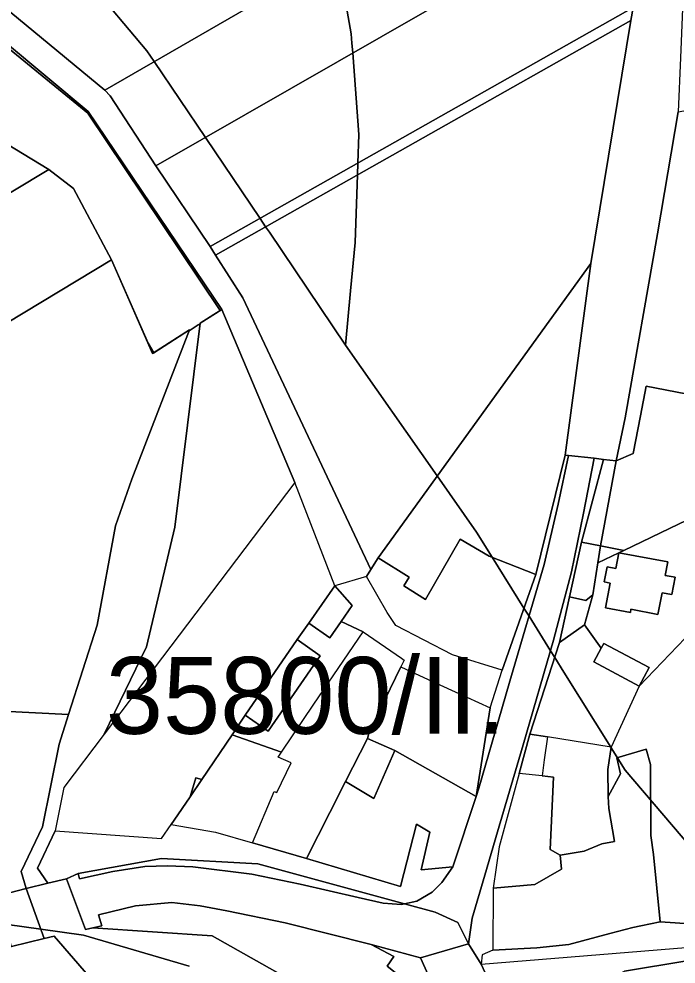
# Model space of a CAD drawing. Extents: x -522079 to -518792, y -1142400 to -1139961.
# Drawn here: x -520476.1 to -520347.8, y -1140798.1 to -1140613.6 of the extents above; entities that cross this region are included whole.
import ezdxf

# ---------------------------------------------------------------- set-up
doc = ezdxf.new("R2010")
doc.units = 0
for name, color, linetype in [('Bonity', 7, 'Continuous'), ('Hranice parcel', 7, 'Continuous'), ('Parcelní čísla', 7, 'Continuous'), ('Poz předměty', 7, 'Continuous'), ('Vnitřní kresba', 7, 'Continuous'), ('Značky bodu BP', 7, 'Continuous'), ('Značky kultur', 7, 'Continuous')]:
    doc.layers.add(name, color=color, linetype=linetype)

msp = doc.modelspace()

# ---------------------------------------------------------------- linework, layer by layer
at = {"layer": 'Bonity'}
msp.add_lwpolyline([(-520482.03, -1140698.6), (-520492.24, -1140681.28), (-520457.96, -1140660.67), (-520449.96, -1140678.96), (-520442.74, -1140674.34), (-520454.03, -1140703.46), (-520457.2, -1140712.56), (-520460.77, -1140732), (-520466.36, -1140749.44), (-520479.24, -1140748.79), (-520495.27, -1140747.98), (-520489.4, -1140725.83), (-520488.36, -1140721.89)], close=True, dxfattribs=at)
at = {"layer": 'Hranice parcel'}
for points in [[(-520307.77, -1140486.46), (-520327.66, -1140534.75), (-520331.42, -1140543.88), (-520333.94, -1140551.84), (-520337.95, -1140565.45), (-520342.68, -1140587.14), (-520346.39, -1140608.35), (-520346.89, -1140621.24), (-520347.36, -1140631.75), (-520351.39, -1140655.57), (-520357.72, -1140691.49), (-520359.48, -1140699.91), (-520361.97, -1140699.61), (-520363.79, -1140699.4), (-520368.79, -1140698.83), (-520369.41, -1140698.76), (-520364.42, -1140661.36), (-520356.59, -1140613.91), (-520356.14, -1140611.39), (-520352.4, -1140586.73), (-520348.21, -1140563.43), (-520342.62, -1140543.01), (-520328.73, -1140508.82)], [(-520587.65, -1140510.13), (-520562.49, -1140540.48), (-520557.7, -1140546.26), (-520503.8, -1140590.78), (-520490.09, -1140602.11), (-520459.31, -1140627.54), (-520458.26, -1140628.64), (-520449.35, -1140642.33), (-520438.76, -1140658.07), (-520437.69, -1140659.73), (-520432.32, -1140668.06), (-520407.37, -1140721.08), (-520408.23, -1140722.45), (-520414.39, -1140724.32), (-520422.23, -1140704.1), (-520436.48, -1140670.33), (-520462.54, -1140631.68), (-520560.63, -1140549.81), (-520611.7, -1140490.5)], [(-520408.23, -1140722.45), (-520414.39, -1140724.32)], [(-520381.74, -1140740.77), (-520391.43, -1140737.8), (-520402.49, -1140732.06), (-520404.15, -1140729.51), (-520408.23, -1140722.45)], [(-520414.39, -1140724.32), (-520419.44, -1140731.56)], [(-520413.15, -1140731.24), (-520410.99, -1140728.16), (-520414.39, -1140724.32)], [(-520414.39, -1140724.32), (-520410.99, -1140728.16), (-520413.15, -1140731.24)], [(-520419.44, -1140731.56), (-520421.72, -1140734.81)], [(-520419.44, -1140731.56), (-520415.38, -1140734.43)], [(-520415.38, -1140734.43), (-520419.44, -1140731.56)], [(-520415.38, -1140734.43), (-520413.15, -1140731.24)], [(-520413.15, -1140731.24), (-520415.38, -1140734.43)], [(-520413.15, -1140731.24), (-520408.83, -1140733.26)], [(-520408.83, -1140733.26), (-520413.15, -1140731.24)], [(-520424.83, -1140756.78), (-520418.47, -1140747.39), (-520408.83, -1140733.26)], [(-520408.83, -1140733.26), (-520401.38, -1140738.43), (-520400.87, -1140738.78), (-520401.52, -1140740.13)], [(-520421.72, -1140734.81), (-520431.9, -1140749.57)], [(-520417.23, -1140737.96), (-520421.72, -1140734.81)], [(-520421.72, -1140734.81), (-520417.23, -1140737.96)], [(-520427.38, -1140752.69), (-520417.23, -1140737.96)], [(-520417.23, -1140737.96), (-520427.38, -1140752.69)], [(-520401.52, -1140740.13), (-520396.18, -1140742.58), (-520390.88, -1140745.01), (-520384.05, -1140748.14)], [(-520384.05, -1140748.14), (-520381.74, -1140740.77)], [(-520431.9, -1140749.57), (-520434.44, -1140753.41)], [(-520431.9, -1140749.57), (-520427.38, -1140752.69)], [(-520427.38, -1140752.69), (-520431.9, -1140749.57)], [(-520434.44, -1140753.41), (-520440.36, -1140762.11)], [(-520434.44, -1140753.41), (-520424.83, -1140756.78)], [(-520424.83, -1140756.78), (-520434.44, -1140753.41)], [(-520372.89, -1140753.81), (-520373.51, -1140758.29), (-520373.94, -1140761.39)], [(-520360.42, -1140755.8), (-520372.89, -1140753.81)], [(-520361.04, -1140765.41), (-520361.11, -1140760.14), (-520360.42, -1140755.8)], [(-520350.89, -1140789.92), (-520352.17, -1140776.77), (-520352.71, -1140773.02), (-520352.78, -1140759.2), (-520353.64, -1140756.21), (-520359.31, -1140757.88), (-520358.59, -1140760.98), (-520361.04, -1140765.41)], [(-520430.49, -1140774.45), (-520426.25, -1140764.44), (-520425.69, -1140764.63), (-520422.94, -1140758.87), (-520425.43, -1140757.74), (-520424.83, -1140756.78)], [(-520440.36, -1140762.11), (-520441.56, -1140761.77), (-520442.66, -1140765.49)], [(-520373.94, -1140761.39), (-520371.72, -1140761.64), (-520372.32, -1140775.75), (-520370.42, -1140776.86)], [(-520442.66, -1140765.49), (-520440.36, -1140762.11)], [(-520440.36, -1140762.11), (-520442.66, -1140765.49)], [(-520442.66, -1140765.49), (-520445.76, -1140770.03), (-520446.34, -1140770.88)], [(-520370.42, -1140776.86), (-520365.71, -1140776.1), (-520362.27, -1140774.68), (-520359.77, -1140774.23), (-520360.88, -1140767.78), (-520361.04, -1140765.41)], [(-520361.04, -1140765.41), (-520360.88, -1140767.78), (-520359.77, -1140774.23)], [(-520626.37, -1140766.52), (-520614.11, -1140775.58), (-520593.15, -1140785.04), (-520568.68, -1140791.66), (-520556.98, -1140793.85), (-520544.08, -1140795.45), (-520533.1, -1140795.95), (-520521.89, -1140795.42), (-520508.09, -1140793.94), (-520497.35, -1140791.93), (-520485.15, -1140788.87), (-520482.88, -1140787.7), (-520480.98, -1140785.01), (-520474.64, -1140783.36), (-520471.14, -1140793.15), (-520477.5, -1140794.69), (-520477.93, -1140793.38), (-520487.57, -1140796.09), (-520495.6, -1140797.79), (-520508.3, -1140799.99)], [(-520446.34, -1140770.88), (-520437.68, -1140772.4), (-520430.49, -1140774.45)], [(-520362.27, -1140774.68), (-520365.71, -1140776.1)], [(-520359.77, -1140774.23), (-520362.27, -1140774.68)], [(-520365.71, -1140776.1), (-520370.42, -1140776.86)], [(-520370.42, -1140776.86), (-520370.11, -1140779.64), (-520375.33, -1140782.59)], [(-520383.46, -1140783.32), (-520383.53, -1140795.4)], [(-520375.33, -1140782.59), (-520383.46, -1140783.32)], [(-520368.73, -1140794.29), (-520360.72, -1140792.17), (-520356.2, -1140791.03), (-520354.62, -1140790.65), (-520350.89, -1140789.92)], [(-520350.89, -1140789.92), (-520354.62, -1140790.65), (-520356.2, -1140791.03), (-520360.72, -1140792.17), (-520368.73, -1140794.29)], [(-520332.51, -1140791.1), (-520350.89, -1140789.92)], [(-520385.85, -1140798.14), (-520333.88, -1140793.93), (-520323.97, -1140803.87)], [(-520383.53, -1140795.4), (-520374.96, -1140794.94), (-520368.73, -1140794.29)], [(-520368.73, -1140794.29), (-520374.96, -1140794.94), (-520383.53, -1140795.4)], [(-520383.53, -1140795.4), (-520385.62, -1140796.31), (-520385.85, -1140798.14)]]:
    msp.add_lwpolyline(points, dxfattribs=at)
for points in [[(-520343.7, -1140699.72), (-520340.94, -1140698.56), (-520339.07, -1140702.89), (-520335.84, -1140701.48), (-520334.3, -1140706.02), (-520336.43, -1140707.04), (-520344.29, -1140710.82), (-520347.29, -1140712.26), (-520357.97, -1140717.4), (-520362.54, -1140716.5), (-520359.48, -1140699.91), (-520356.12, -1140698.44), (-520354.71, -1140691.1), (-520353.6, -1140685.32), (-520345.87, -1140686.81), (-520341.7, -1140687.61), (-520339.66, -1140692.44), (-520345.67, -1140694.97)], [(-520394.79, -1140788), (-520400.82, -1140786.35), (-520398.38, -1140785.83), (-520395.36, -1140784.1), (-520393.48, -1140782.23), (-520391.38, -1140779.15), (-520386.83, -1140765.41), (-520386.29, -1140763.79), (-520381.78, -1140748.3), (-520380.21, -1140742.93), (-520373.52, -1140720.12), (-520370.77, -1140708.37), (-520368.79, -1140698.83), (-520363.79, -1140699.4), (-520365.84, -1140710.09), (-520368.19, -1140721.56), (-520371.69, -1140734.94), (-520377.6, -1140755.34), (-520382.64, -1140772.35), (-520385.08, -1140780.78), (-520387.56, -1140789.2), (-520388.29, -1140794.2), (-520390.4, -1140790.05)], [(-520386.83, -1140765.41), (-520384.05, -1140748.14), (-520381.74, -1140740.77), (-520375.15, -1140722.06), (-520369.41, -1140698.76), (-520368.79, -1140698.83), (-520370.77, -1140708.37), (-520373.52, -1140720.12), (-520380.21, -1140742.93), (-520381.78, -1140748.3), (-520386.29, -1140763.79)], [(-520383.46, -1140783.32), (-520383.53, -1140795.4), (-520385.62, -1140796.31), (-520385.85, -1140798.14), (-520388.29, -1140794.2), (-520387.56, -1140789.2), (-520385.08, -1140780.78), (-520382.64, -1140772.35), (-520377.6, -1140755.34), (-520371.69, -1140734.94), (-520368.19, -1140721.56), (-520365.84, -1140710.09), (-520363.79, -1140699.4), (-520361.97, -1140699.61), (-520366.26, -1140715.78), (-520368.57, -1140726.47), (-520370.5, -1140735.37), (-520376.29, -1140753.27), (-520378.38, -1140760.91), (-520382.29, -1140775.26)], [(-520366.26, -1140715.78), (-520361.97, -1140699.61), (-520359.48, -1140699.91), (-520362.54, -1140716.5)], [(-520381.74, -1140740.77), (-520391.43, -1140737.8), (-520402.49, -1140732.06), (-520404.15, -1140729.51), (-520408.23, -1140722.45), (-520407.37, -1140721.08), (-520405.96, -1140718.81), (-520399.85, -1140722.62), (-520400.9, -1140724.3), (-520396.68, -1140726.94), (-520389.9, -1140715.22), (-520384.29, -1140718.48), (-520375.15, -1140722.06)], [(-520368.57, -1140726.47), (-520366.26, -1140715.78), (-520362.54, -1140716.5), (-520363.02, -1140719.82), (-520364.02, -1140726.04), (-520365.37, -1140727.18)], [(-520357.97, -1140717.4), (-520358.95, -1140717.87), (-520363.02, -1140719.82), (-520362.54, -1140716.5)], [(-520358.95, -1140717.87), (-520349.37, -1140719.63), (-520349.88, -1140722.27), (-520347.97, -1140722.63), (-520348.59, -1140726.01), (-520350.51, -1140725.65), (-520351.32, -1140729.89), (-520356.58, -1140728.88), (-520356.67, -1140729.48), (-520361.57, -1140728.6), (-520360.67, -1140723.75), (-520361.8, -1140723.5), (-520361.21, -1140720.62), (-520359.53, -1140720.91)], [(-520365.37, -1140727.18), (-520364.02, -1140726.04), (-520365.68, -1140731.9), (-520370.5, -1140735.37), (-520368.57, -1140726.47)], [(-520365.68, -1140731.9), (-520362.41, -1140736.49), (-520363.84, -1140739.14), (-520354.98, -1140743.86), (-520360.42, -1140755.8), (-520372.89, -1140753.81), (-520376.29, -1140753.27), (-520370.5, -1140735.37)], [(-520407.68, -1140752.84), (-520408.04, -1140754.09), (-520412.32, -1140762.52), (-520415.37, -1140768.55), (-520419.92, -1140777.53), (-520430.49, -1140774.45), (-520426.25, -1140764.44), (-520425.69, -1140764.63), (-520422.94, -1140758.87), (-520425.43, -1140757.74), (-520424.83, -1140756.78), (-520418.47, -1140747.39), (-520408.83, -1140733.26), (-520401.38, -1140738.43), (-520400.87, -1140738.78), (-520401.52, -1140740.13)], [(-520361.88, -1140735.57), (-520353.05, -1140740.25), (-520354.98, -1140743.86), (-520363.84, -1140739.14), (-520362.41, -1140736.49)], [(-520386.83, -1140765.41), (-520402.66, -1140756.46), (-520408.04, -1140754.09), (-520407.68, -1140752.84), (-520401.52, -1140740.13), (-520396.18, -1140742.58), (-520390.88, -1140745.01), (-520384.05, -1140748.14)], [(-520480.98, -1140785.01), (-520484.92, -1140786.1), (-520485.38, -1140782.23), (-520498.09, -1140783.57), (-520499.08, -1140774.22), (-520498.32, -1140766.26), (-520497.66, -1140759.42), (-520497.51, -1140757.87), (-520496.94, -1140755.37), (-520495.27, -1140747.98), (-520479.24, -1140748.79), (-520466.36, -1140749.44), (-520468.2, -1140755.18), (-520471.47, -1140771.35), (-520475.64, -1140780.08), (-520474.64, -1140783.36)], [(-520412.32, -1140762.52), (-520408.04, -1140754.09), (-520402.66, -1140756.46), (-520406.78, -1140765.84)], [(-520372.89, -1140753.81), (-520373.51, -1140758.29), (-520373.94, -1140761.39), (-520378.38, -1140760.91), (-520376.29, -1140753.27)], [(-520419.92, -1140777.53), (-520415.37, -1140768.55), (-520412.32, -1140762.52), (-520406.78, -1140765.84), (-520402.66, -1140756.46), (-520386.83, -1140765.41), (-520391.38, -1140779.15), (-520397.56, -1140779.72), (-520395.82, -1140772.4), (-520398.45, -1140770.83), (-520401.54, -1140783.02)], [(-520470.41, -1140782.37), (-520472.47, -1140779.4), (-520468.98, -1140772.14), (-520448.2, -1140773.61), (-520446.34, -1140770.88), (-520437.68, -1140772.4), (-520430.49, -1140774.45), (-520419.92, -1140777.53), (-520401.54, -1140783.02), (-520398.45, -1140770.83), (-520395.82, -1140772.4), (-520397.56, -1140779.72), (-520391.38, -1140779.15), (-520393.48, -1140782.23), (-520395.36, -1140784.1), (-520398.38, -1140785.83), (-520400.82, -1140786.35), (-520429.44, -1140778.54), (-520448.23, -1140777.51), (-520464.48, -1140780.47), (-520466.78, -1140781.53)], [(-520400.82, -1140786.35), (-520401.42, -1140786.48), (-520404.95, -1140786.22), (-520409.82, -1140785.14), (-520421.16, -1140782.56), (-520430.59, -1140780.58), (-520442.14, -1140779.17), (-520447.03, -1140778.94), (-520451.46, -1140779.1), (-520457.74, -1140780.06), (-520464.21, -1140781.48), (-520464.48, -1140780.47), (-520448.23, -1140777.51), (-520429.44, -1140778.54)], [(-520407.29, -1140794.34), (-520424.08, -1140790.09), (-520435.45, -1140787.73), (-520440.68, -1140786.74), (-520446.22, -1140786.13), (-520453.31, -1140786.74), (-520460.51, -1140788.53), (-520459.9, -1140790.65), (-520461.64, -1140791.05), (-520463.08, -1140791.37), (-520466.78, -1140781.53), (-520464.48, -1140780.47), (-520464.21, -1140781.48), (-520457.74, -1140780.06), (-520451.46, -1140779.1), (-520447.03, -1140778.94), (-520442.14, -1140779.17), (-520430.59, -1140780.58), (-520421.16, -1140782.56), (-520409.82, -1140785.14), (-520404.95, -1140786.22), (-520401.42, -1140786.48), (-520400.82, -1140786.35), (-520394.79, -1140788), (-520390.4, -1140790.05), (-520388.29, -1140794.2), (-520397.69, -1140796.9)], [(-520461.64, -1140791.05), (-520459.9, -1140790.65), (-520460.51, -1140788.53), (-520453.31, -1140786.74), (-520446.22, -1140786.13), (-520440.68, -1140786.74), (-520435.45, -1140787.73), (-520424.08, -1140790.09), (-520407.29, -1140794.34), (-520402.86, -1140796.64), (-520404.19, -1140798.55), (-520401.05, -1140800.99), (-520400.31, -1140802.09), (-520404.93, -1140803.86), (-520413.92, -1140809.23), (-520421.04, -1140802.37), (-520438.34, -1140792.64)], [(-520479.52, -1140802.35), (-520481.31, -1140802.54), (-520492.42, -1140803.71), (-520483.65, -1140796.14), (-520478.64, -1140794.97), (-520477.5, -1140794.69), (-520471.14, -1140793.15), (-520469.2, -1140792.72), (-520462.48, -1140800.42), (-520444.45, -1140805.57), (-520456.93, -1140810.9), (-520471.87, -1140801.78), (-520475.9, -1140802.08)], [(-520402.86, -1140796.64), (-520407.29, -1140794.34), (-520397.69, -1140796.9), (-520396.18, -1140800.22), (-520397.88, -1140801.13), (-520400.31, -1140802.09), (-520401.05, -1140800.99), (-520404.19, -1140798.55)], [(-520377.1, -1140813.45), (-520380.6, -1140811.79), (-520380.67, -1140811.43), (-520380.39, -1140811.76), (-520379.96, -1140811.88), (-520378.82, -1140811.8), (-520377.82, -1140811.29), (-520380.85, -1140806.63), (-520373.88, -1140807.82), (-520357.86, -1140799.52), (-520345.68, -1140797.53), (-520334.95, -1140799.21), (-520328.7, -1140804.9)]]:
    msp.add_lwpolyline(points, close=True, dxfattribs=at)
at = {"layer": 'Parcelní čísla'}
for points in [[(-520459.31, -1140627.54), (-520490.09, -1140602.11), (-520328.73, -1140508.82), (-520342.62, -1140543.01), (-520348.21, -1140563.43)], [(-520449.35, -1140642.33), (-520352.4, -1140586.73), (-520356.14, -1140611.39), (-520438.76, -1140658.07)], [(-520356.14, -1140611.39), (-520356.59, -1140613.91), (-520437.69, -1140659.73), (-520438.76, -1140658.07)], [(-520356.59, -1140613.91), (-520364.42, -1140661.36), (-520405.96, -1140718.81), (-520407.37, -1140721.08), (-520432.32, -1140668.06), (-520437.69, -1140659.73)]]:
    msp.add_lwpolyline(points, close=True, dxfattribs=at)
at = {"layer": 'Poz předměty'}
for points in [[(-520598.21, -1140690.89), (-520487.78, -1140623.27), (-520481.74, -1140636.06), (-520470.21, -1140643.01), (-520586.97, -1140713.22)], [(-520553.91, -1140708.56), (-520579.53, -1140724.2), (-520579.01, -1140725.05), (-520580.64, -1140725.97), (-520586.97, -1140713.22), (-520470.21, -1140643.01), (-520465.4, -1140646.75), (-520457.96, -1140660.67), (-520492.24, -1140681.28), (-520531.99, -1140705.14), (-520549.51, -1140715.7), (-520553.39, -1140709.41)]]:
    msp.add_lwpolyline(points, close=True, dxfattribs=at)
at = {"layer": 'Vnitřní kresba'}
for points in [[(-520560.63, -1140549.81), (-520462.54, -1140631.68), (-520436.48, -1140670.33), (-520440.71, -1140673.04), (-520445.6, -1140712.87), (-520451.15, -1140736.24), (-520459.41, -1140753.25), (-520467.31, -1140763.69), (-520468.98, -1140772.14), (-520472.47, -1140779.4), (-520470.41, -1140782.37), (-520474.64, -1140783.36), (-520475.64, -1140780.08), (-520471.47, -1140771.35), (-520468.2, -1140755.18), (-520466.36, -1140749.44), (-520460.77, -1140732), (-520457.2, -1140712.56), (-520454.03, -1140703.46), (-520442.74, -1140674.34), (-520449.96, -1140678.96), (-520457.96, -1140660.67), (-520465.4, -1140646.75), (-520470.21, -1140643.01), (-520481.74, -1140636.06)], [(-520462.48, -1140800.42), (-520469.2, -1140792.72), (-520471.14, -1140793.15), (-520474.64, -1140783.36), (-520470.41, -1140782.37), (-520466.78, -1140781.53), (-520463.08, -1140791.37), (-520461.64, -1140791.05), (-520438.34, -1140792.64), (-520421.04, -1140802.37)], [(-520396.18, -1140800.22), (-520397.69, -1140796.9), (-520388.29, -1140794.2), (-520385.85, -1140798.14), (-520384.61, -1140800.83)], [(-520384.61, -1140800.83), (-520385.85, -1140798.14), (-520333.88, -1140793.93), (-520323.97, -1140803.87)], [(-520334.95, -1140799.21), (-520345.68, -1140797.53), (-520357.86, -1140799.52)]]:
    msp.add_lwpolyline(points, dxfattribs=at)
at = {"layer": 'Značky bodu BP'}
for points in [[(-520509.5, -1140601.29), (-520492.51, -1140614.6), (-520487.78, -1140623.27), (-520481.74, -1140636.06), (-520470.21, -1140643.01), (-520465.4, -1140646.75), (-520457.96, -1140660.67), (-520450.83, -1140676.96), (-520449.76, -1140678.83), (-520442.74, -1140674.34), (-520442.82, -1140674.54), (-520441.08, -1140673.37), (-520440.84, -1140673.23), (-520440.72, -1140673.16), (-520440.71, -1140673.04), (-520436.78, -1140670.52), (-520444.58, -1140658.9), (-520462.62, -1140632.02), (-520562.29, -1140550.47)], [(-520562.29, -1140550.47), (-520462.62, -1140632.02), (-520444.58, -1140658.9), (-520436.78, -1140670.52), (-520440.71, -1140673.04), (-520440.72, -1140673.16), (-520440.84, -1140673.23), (-520441.08, -1140673.37), (-520442.82, -1140674.54), (-520442.74, -1140674.34), (-520449.76, -1140678.83), (-520450.83, -1140676.96), (-520457.96, -1140660.67), (-520465.4, -1140646.75), (-520470.21, -1140643.01), (-520481.74, -1140636.06), (-520487.78, -1140623.27), (-520492.51, -1140614.6), (-520509.5, -1140601.29)], [(-520473.9, -1140592.75), (-520451.08, -1140619.87), (-520449.66, -1140621.97), (-520439.66, -1140636.77), (-520429, -1140652.56), (-520427.9, -1140654.19), (-520427.16, -1140655.28), (-520412.29, -1140677.3), (-520394.42, -1140702.84), (-520386.74, -1140713.8), (-520383.67, -1140718.72), (-520377.47, -1140728.65), (-520376.48, -1140730.23), (-520372.28, -1140736.96), (-520371.45, -1140738.29), (-520369.67, -1140741.14), (-520360.52, -1140755.78), (-520360.44, -1140755.92), (-520357.72, -1140760.26), (-520339.2, -1140781.94)], [(-520413.86, -1140601.32), (-520411.19, -1140616.53), (-520411.05, -1140618.35), (-520410.9, -1140620.28), (-520409.71, -1140636.17), (-520409.9, -1140641.76), (-520409.98, -1140644.08), (-520410.25, -1140651.6), (-520410.45, -1140657.29), (-520411.31, -1140666.69), (-520412.29, -1140677.3), (-520427.16, -1140655.28), (-520427.9, -1140654.19), (-520429, -1140652.56), (-520439.66, -1140636.77), (-520449.66, -1140621.97), (-520451.08, -1140619.87), (-520473.9, -1140592.75)], [(-520339.2, -1140781.94), (-520357.72, -1140760.26), (-520360.44, -1140755.92), (-520360.52, -1140755.78), (-520369.67, -1140741.14), (-520371.45, -1140738.29), (-520372.28, -1140736.96), (-520376.48, -1140730.23), (-520377.47, -1140728.65), (-520383.67, -1140718.72), (-520386.74, -1140713.8), (-520394.42, -1140702.84), (-520412.29, -1140677.3), (-520411.31, -1140666.69), (-520410.45, -1140657.29), (-520410.25, -1140651.6), (-520409.98, -1140644.08), (-520409.9, -1140641.76), (-520409.71, -1140636.17), (-520410.9, -1140620.28), (-520411.05, -1140618.35), (-520411.19, -1140616.53), (-520413.86, -1140601.32)], [(-520442.83, -1140798.57), (-520463.48, -1140792.48), (-520471.79, -1140791.32), (-520485.34, -1140789.43)], [(-520485.34, -1140789.43), (-520471.79, -1140791.32), (-520463.48, -1140792.48), (-520442.83, -1140798.57)]]:
    msp.add_lwpolyline(points, dxfattribs=at)
at = {"layer": 'Značky kultur'}
for points in [[(-520449.35, -1140642.33), (-520458.26, -1140628.64), (-520459.31, -1140627.54), (-520348.21, -1140563.43), (-520352.4, -1140586.73)], [(-520359.48, -1140699.91), (-520357.72, -1140691.49), (-520351.39, -1140655.57), (-520347.36, -1140631.75), (-520343.28, -1140631.04), (-520324.4, -1140655.71), (-520303.56, -1140683.6), (-520326.31, -1140701.14), (-520334.3, -1140706.02), (-520335.84, -1140701.48), (-520339.66, -1140692.44), (-520341.7, -1140687.61), (-520345.87, -1140686.81), (-520353.6, -1140685.32), (-520354.71, -1140691.1), (-520356.12, -1140698.44)], [(-520375.15, -1140722.06), (-520384.29, -1140718.48), (-520389.9, -1140715.22), (-520396.68, -1140726.94), (-520400.9, -1140724.3), (-520399.85, -1140722.62), (-520405.96, -1140718.81), (-520364.42, -1140661.36), (-520369.41, -1140698.76)], [(-520459.41, -1140753.25), (-520451.15, -1140736.24), (-520445.6, -1140712.87), (-520440.71, -1140673.04), (-520436.48, -1140670.33), (-520422.23, -1140704.1)], [(-520322.69, -1140705.99), (-520320.58, -1140707.95), (-520354.98, -1140743.86), (-520353.05, -1140740.25), (-520361.88, -1140735.57), (-520362.41, -1140736.49), (-520365.68, -1140731.9), (-520364.02, -1140726.04), (-520363.02, -1140719.82), (-520358.95, -1140717.87), (-520357.97, -1140717.4), (-520347.29, -1140712.26), (-520344.29, -1140710.82), (-520336.43, -1140707.04), (-520334.3, -1140706.02)], [(-520358.95, -1140717.87), (-520359.53, -1140720.91), (-520361.21, -1140720.62), (-520361.8, -1140723.5), (-520360.67, -1140723.75), (-520361.57, -1140728.6), (-520356.67, -1140729.48), (-520356.58, -1140728.88), (-520351.32, -1140729.89), (-520350.51, -1140725.65), (-520348.59, -1140726.01), (-520347.97, -1140722.63), (-520349.88, -1140722.27), (-520349.37, -1140719.63)]]:
    msp.add_lwpolyline(points, close=True, dxfattribs=at)
for points in [[(-520422.23, -1140704.1), (-520459.41, -1140753.25)], [(-520414.39, -1140724.32), (-520422.23, -1140704.1)], [(-520320.58, -1140707.95), (-520354.98, -1140743.86)], [(-520419.44, -1140731.56), (-520414.39, -1140724.32)], [(-520421.72, -1140734.81), (-520419.44, -1140731.56)], [(-520431.9, -1140749.57), (-520421.72, -1140734.81)], [(-520354.98, -1140743.86), (-520360.42, -1140755.8)], [(-520434.44, -1140753.41), (-520431.9, -1140749.57)], [(-520459.41, -1140753.25), (-520467.31, -1140763.69), (-520468.98, -1140772.14)], [(-520440.36, -1140762.11), (-520434.44, -1140753.41)], [(-520360.42, -1140755.8), (-520361.11, -1140760.14), (-520361.04, -1140765.41)], [(-520361.04, -1140765.41), (-520358.59, -1140760.98), (-520359.31, -1140757.88), (-520353.64, -1140756.21), (-520352.78, -1140759.2)], [(-520352.78, -1140759.2), (-520352.71, -1140773.02)], [(-520442.66, -1140765.49), (-520441.56, -1140761.77), (-520440.36, -1140762.11)], [(-520378.38, -1140760.91), (-520382.29, -1140775.26), (-520383.46, -1140783.32)], [(-520373.94, -1140761.39), (-520378.38, -1140760.91)], [(-520370.42, -1140776.86), (-520372.32, -1140775.75), (-520371.72, -1140761.64), (-520373.94, -1140761.39)], [(-520445.76, -1140770.03), (-520442.66, -1140765.49)], [(-520468.98, -1140772.14), (-520448.2, -1140773.61), (-520446.34, -1140770.88)], [(-520446.34, -1140770.88), (-520445.76, -1140770.03)], [(-520352.71, -1140773.02), (-520352.17, -1140776.77), (-520350.89, -1140789.92)], [(-520375.33, -1140782.59), (-520370.11, -1140779.64), (-520370.42, -1140776.86)], [(-520383.46, -1140783.32), (-520375.33, -1140782.59)], [(-520350.89, -1140789.92), (-520332.51, -1140791.1), (-520331.09, -1140791.46)]]:
    msp.add_lwpolyline(points, dxfattribs=at)

# ---------------------------------------------------------------- texts
at = {"layer": 'Značky bodu BP'}
msp.add_text('35800/II.', height=15, rotation=0, dxfattribs=at).set_placement((-520459.09, -1140753.19))

doc.saveas('drawing.dxf')
